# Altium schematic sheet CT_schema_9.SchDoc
size 382 x 278 mm
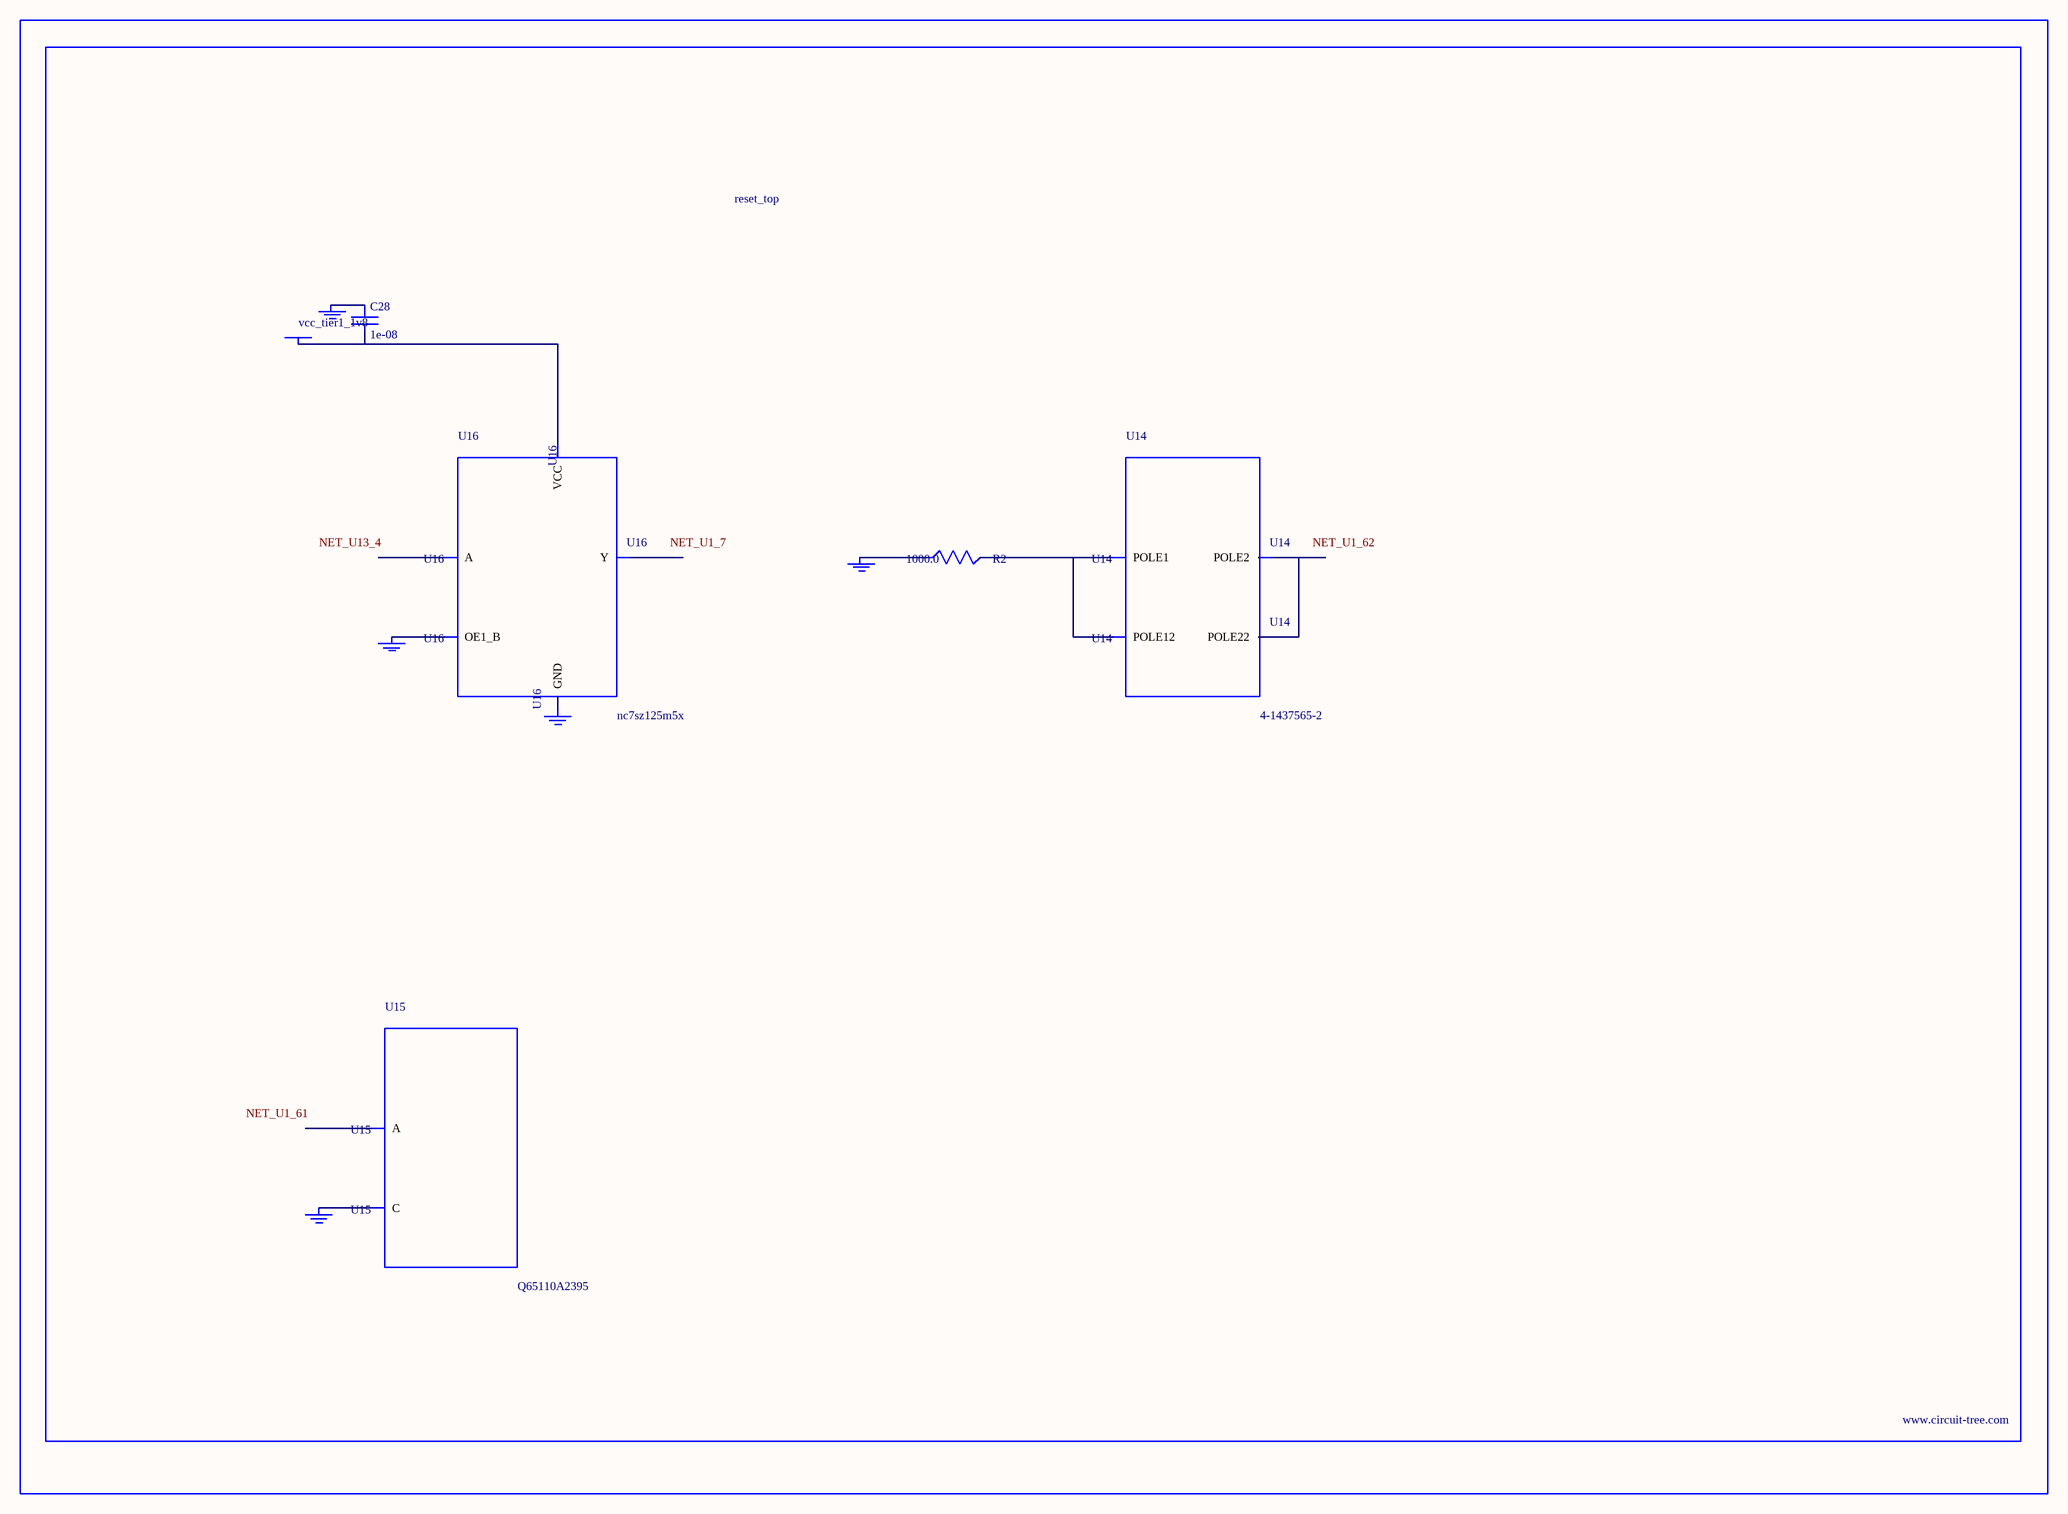
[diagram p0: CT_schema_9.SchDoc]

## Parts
BORDER8  (no value)
C28  1e-08  [C0402]
GND_INSTANCE_8_0  (no value)
GND_INSTANCE_8_1  (no value)
GND_INSTANCE_8_2  (no value)
GND_INSTANCE_8_3  (no value)
GND_INSTANCE_8_4  (no value)
POWER_INSTANCE_8_0  vcc_tier1_1v8
R2  1000.0  [R0603]
U14  4-1437565-2  [SW_4-1437565-2]
U15  Q65110A2395  [LGM67K-G1J2-24-Z]
U16  nc7sz125m5x  [NC7SZ125M5X]

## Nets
NetC28_1: C28.1 GND_INSTANCE_8_2.0(GND)
NetC28_2: C28.2 POWER_INSTANCE_8_0.0(PWR) U16.5(VCC)
NetGND_INSTANCE_8_0_0: GND_INSTANCE_8_0.0(GND) R2.1
NetGND_INSTANCE_8_1_0: GND_INSTANCE_8_1.0(GND) U15.C
NetGND_INSTANCE_8_3_0: GND_INSTANCE_8_3.0(GND) U16.1(OE1_B)
NetGND_INSTANCE_8_4_0: GND_INSTANCE_8_4.0(GND) U16.3(GND)
NetR2_2: R2.2 U14.1(POLE1) U14.2(POLE12)
NetU14_3: U14.3(POLE2) U14.4(POLE22)

Not connected (* = marked no-connect by the designer): U15 A; U16 2(A) 4(Y)

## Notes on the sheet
- Labels drawn without touching a wire or pin: NET_U1_7, NET_U1_61, NET_U1_62, NET_U13_4

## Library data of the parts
BORDER8 = BORDER_PAGE8
C28 = C0402C103K3RAC
GND_INSTANCE_8_0-GND_INSTANCE_8_4 = GND
POWER_INSTANCE_8_0 = PWR
R2 = RC0603JR-071KL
